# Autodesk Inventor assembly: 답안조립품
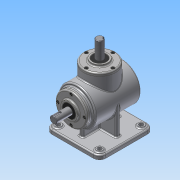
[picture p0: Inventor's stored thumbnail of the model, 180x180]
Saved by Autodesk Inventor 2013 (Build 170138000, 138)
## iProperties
Created: 2015-07
Part Number: 답안조립품
Document SubType Name: Assembly
Designer: Administrator
Author: Administrator
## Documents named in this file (14)
- C:\Users\Administrator\Desktop\450706V1017\답안조립품.iam
- C:\Users\Administrator\Desktop\450706V1017\1.본체.ipt
- C:\Users\Administrator\Desktop\450706V1017\커버.ipt
- C:\Users\Administrator\Desktop\450706V1017\베어링 6203.ipt
- C:\Users\Administrator\Desktop\450706V1017\오일실.ipt
- C:\Users\Administrator\Desktop\450706V1017\M4.ipt
- C:\Users\Administrator\Desktop\450706V1017\메인 축.ipt
- 메인 축.ipt
- C:\Users\Administrator\Desktop\450706V1017\서브 축.ipt
- 서브 축.ipt
- C:\Users\Administrator\Desktop\450706V1017\메인 베벨기어.ipt
- C:\Users\Administrator\Desktop\450706V1017\키 5x5.ipt
- C:\Users\Administrator\Desktop\450706V1017\서브 베벨기어.ipt
- C:\Users\Administrator\Desktop\450706V1017\키 4x4.ipt
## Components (9 placed, 2 different names)
1. 1.본체:1
2. M4:1
3. M4:2
4. M4:3
5. M4:4
6. M4:5
7. M4:6
8. M4:7
9. M4:8
